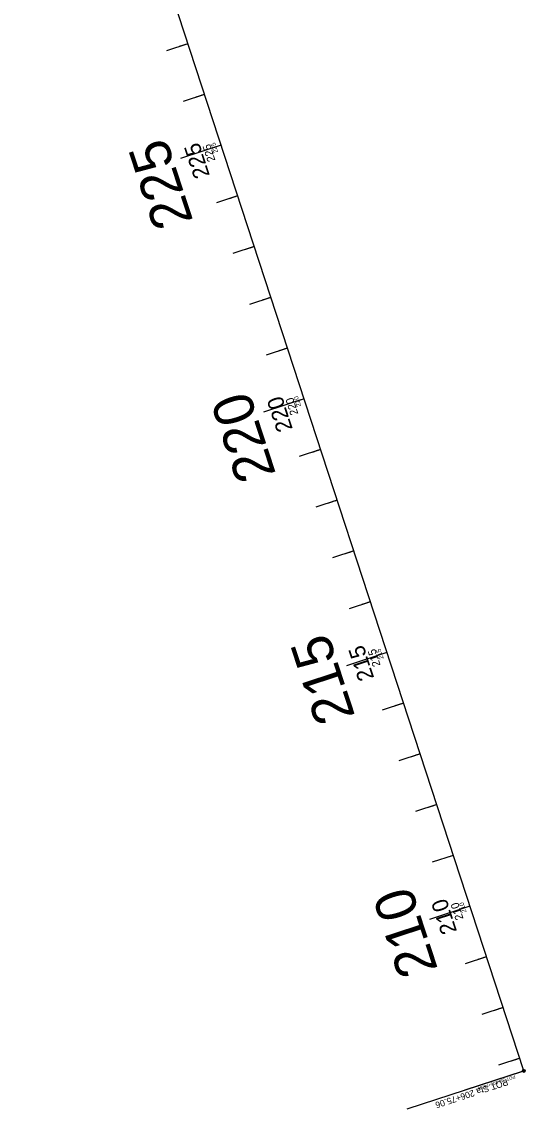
# Model space of a CAD drawing. Extents: x 2358865 to 2362945, y 393485 to 404880.
# Drawn here: x 2359314 to 2360259, y 393485 to 395523 of the extents above; entities that cross this region are included whole.
import ezdxf

# ---------------------------------------------------------------- set-up
doc = ezdxf.new("R2010")
doc.units = 0
for name, color, linetype in [('CL', 7, 'Continuous'), ('Level 25', 7, 'Continuous'), ('Level 28', 7, 'Continuous'), ('Level 30', 7, 'Continuous'), ('Level 33', 7, 'Continuous'), ('Level 39', 7, 'Continuous'), ('Level 41', 7, 'Continuous')]:
    doc.layers.add(name, color=color, linetype=linetype)

msp = doc.modelspace()

# ---------------------------------------------------------------- linework, layer by layer
at = {"layer": 'CL'}
msp.add_line((2360255.9, 393557.3), (2359314.4, 396433.7), dxfattribs=at)
at = {"layer": 'Level 25'}
for p, q in [((2359626, 395481.8), (2359621.2, 395480.2)), ((2359657.1, 395386.7), (2359652.3, 395385.2)), ((2359688.2, 395291.7), (2359680.6, 395289.2)), ((2359719.3, 395196.6), (2359714.6, 395195.1)), ((2359750.4, 395101.6), (2359745.7, 395100)), ((2359781.5, 395006.6), (2359776.8, 395005)), ((2359812.6, 394911.5), (2359807.9, 394910)), ((2359843.7, 394816.5), (2359836.1, 394814)), ((2359874.8, 394721.4), (2359870.1, 394719.9)), ((2359906, 394626.4), (2359901.2, 394624.8)), ((2359937.1, 394531.4), (2359932.3, 394529.8)), ((2359968.2, 394436.3), (2359963.4, 394434.8)), ((2359999.3, 394341.3), (2359991.7, 394338.8)), ((2360030.4, 394246.2), (2360025.6, 394244.7)), ((2360061.5, 394151.2), (2360056.7, 394149.7)), ((2360092.6, 394056.2), (2360087.8, 394054.6)), ((2360123.7, 393961.1), (2360119, 393959.6)), ((2360154.8, 393866.1), (2360147.2, 393863.6)), ((2360185.9, 393771.1), (2360181.2, 393769.5)), ((2360217, 393676), (2360212.3, 393674.5)), ((2360248.1, 393581), (2360243.4, 393579.4))]:
    msp.add_line(p, q, dxfattribs=at)
at = {"layer": 'Level 28'}
msp.add_line((2360254.7, 393556.9), (2360145.1, 393521), dxfattribs=at)
msp.add_circle((2360255.9, 393557.3), 1.25, dxfattribs=at)
at = {"layer": 'Level 30'}
for p, q in [((2359626, 395481.8), (2359617.9, 395479.1)), ((2359657.1, 395386.7), (2359649, 395384.1)), ((2359688.2, 395291.7), (2359673, 395286.7)), ((2359719.3, 395196.6), (2359711.2, 395194)), ((2359750.4, 395101.6), (2359742.3, 395099)), ((2359781.5, 395006.6), (2359773.4, 395003.9)), ((2359812.6, 394911.5), (2359804.6, 394908.9)), ((2359843.7, 394816.5), (2359828.5, 394811.5)), ((2359874.8, 394721.4), (2359866.8, 394718.8)), ((2359906, 394626.4), (2359897.9, 394623.8)), ((2359937.1, 394531.4), (2359929, 394528.7)), ((2359968.2, 394436.3), (2359960.1, 394433.7)), ((2359999.3, 394341.3), (2359984.1, 394336.3)), ((2360030.4, 394246.2), (2360022.3, 394243.6)), ((2360061.5, 394151.2), (2360053.4, 394148.6)), ((2360092.6, 394056.2), (2360084.5, 394053.5)), ((2360123.7, 393961.1), (2360115.6, 393958.5)), ((2360154.8, 393866.1), (2360139.6, 393861.1)), ((2360185.9, 393771.1), (2360177.8, 393768.4)), ((2360217, 393676), (2360209, 393673.4)), ((2360248.1, 393581), (2360240.1, 393578.3))]:
    msp.add_line(p, q, dxfattribs=at)
at = {"layer": 'Level 33'}
msp.add_line((2360253.3, 393556.4), (2360036.4, 393485.4), dxfattribs=at)
msp.add_circle((2360255.9, 393557.3), 2.7, dxfattribs=at)
at = {"layer": 'Level 39'}
for p, q in [((2359626, 395481.8), (2359609.8, 395476.5)), ((2359657.1, 395386.7), (2359640.9, 395381.4)), ((2359688.2, 395291.7), (2359657.8, 395281.7)), ((2359719.3, 395196.6), (2359703.2, 395191.3)), ((2359750.4, 395101.6), (2359734.3, 395096.3)), ((2359781.5, 395006.6), (2359765.4, 395001.3)), ((2359812.6, 394911.5), (2359796.5, 394906.2)), ((2359843.7, 394816.5), (2359813.3, 394806.5)), ((2359874.8, 394721.4), (2359858.7, 394716.2)), ((2359906, 394626.4), (2359889.8, 394621.1)), ((2359937.1, 394531.4), (2359920.9, 394526.1)), ((2359968.2, 394436.3), (2359952, 394431)), ((2359999.3, 394341.3), (2359968.9, 394331.3)), ((2360030.4, 394246.2), (2360014.2, 394241)), ((2360061.5, 394151.2), (2360045.3, 394145.9)), ((2360092.6, 394056.2), (2360076.4, 394050.9)), ((2360123.7, 393961.1), (2360107.6, 393955.8)), ((2360154.8, 393866.1), (2360124.4, 393856.1)), ((2360185.9, 393771.1), (2360169.8, 393765.8)), ((2360217, 393676), (2360200.9, 393670.7)), ((2360248.1, 393581), (2360232, 393575.7))]:
    msp.add_line(p, q, dxfattribs=at)
at = {"layer": 'Level 41'}
for p, q in [((2359626, 395481.8), (2359586.1, 395468.7)), ((2359657.1, 395386.7), (2359617.2, 395373.6)), ((2359688.2, 395291.7), (2359612.2, 395266.8)), ((2359719.3, 395196.6), (2359679.4, 395183.6)), ((2359750.4, 395101.6), (2359710.5, 395088.5)), ((2359781.5, 395006.6), (2359741.6, 394993.5)), ((2359812.6, 394911.5), (2359772.7, 394898.5)), ((2359843.7, 394816.5), (2359767.7, 394791.6)), ((2359874.8, 394721.4), (2359834.9, 394708.4)), ((2359906, 394626.4), (2359866, 394613.3)), ((2359937.1, 394531.4), (2359897.1, 394518.3)), ((2359968.2, 394436.3), (2359928.3, 394423.3)), ((2359999.3, 394341.3), (2359923.2, 394316.4)), ((2360030.4, 394246.2), (2359990.5, 394233.2)), ((2360061.5, 394151.2), (2360021.6, 394138.1)), ((2360092.6, 394056.2), (2360052.7, 394043.1)), ((2360123.7, 393961.1), (2360083.8, 393948.1)), ((2360154.8, 393866.1), (2360078.8, 393841.2)), ((2360185.9, 393771.1), (2360146, 393758)), ((2360217, 393676), (2360177.1, 393663)), ((2360248.1, 393581), (2360208.2, 393567.9))]:
    msp.add_line(p, q, dxfattribs=at)

# ---------------------------------------------------------------- texts
at = {"layer": 'Level 25'}
for s, p in [('225', (2359682.9, 395278.3)), ('220', (2359838.4, 394803.2)), ('215', (2359993.2, 394330)), ('210', (2360148.7, 393854.9))]:
    msp.add_text(s, height=8.75, rotation=108.1241, dxfattribs=at).set_placement(p)
at = {"layer": 'Level 28'}
msp.add_text('POT Sta 206+75.06', height=6, rotation=198.1241, dxfattribs=at).set_placement((2360238.7, 393549.5))
at = {"layer": 'Level 30'}
for s, p in [('225', (2359677.8, 395263.3)), ('220', (2359833.3, 394788.4)), ('215', (2359987.4, 394317.4)), ('210', (2360142.9, 393842.5))]:
    msp.add_text(s, height=15, rotation=108.1241, dxfattribs=at).set_placement(p)
at = {"layer": 'Level 33'}
msp.add_text('POT Sta 206+75.06', height=12, rotation=198.1241, dxfattribs=at).set_placement((2360223.9, 393542.6))
at = {"layer": 'Level 39'}
for s, p in [('225', (2359667.4, 395235)), ('220', (2359822.8, 394760.2)), ('215', (2359975.5, 394293.6)), ('210', (2360130.9, 393818.8))]:
    msp.add_text(s, height=30, rotation=108.1241, dxfattribs=at).set_placement(p)
at = {"layer": 'Level 41'}
for s, p in [('225', (2359636.3, 395149.7)), ('220', (2359791.5, 394675.5)), ('215', (2359940, 394221.8)), ('210', (2360095.2, 393747.7))]:
    msp.add_text(s, height=75, rotation=108.1241, dxfattribs=at).set_placement(p)

doc.saveas('drawing.dxf')
